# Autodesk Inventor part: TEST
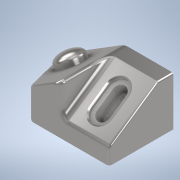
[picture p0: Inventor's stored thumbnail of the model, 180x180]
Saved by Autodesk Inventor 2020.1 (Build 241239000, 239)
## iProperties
Created: 2019-11
Part Number: TEST
Material: Stainless Steel, 440C
Document SubType Name: Modeling
Designer: Synergysoft Dell02
Density: 7.75 g/cm^3
Appearance: Semi-Polished
Author: Synergysoft Dell02
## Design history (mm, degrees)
sketch "Sketch1"
  geometry: L1 (0, 0)-(-62, 0); L2 (-62, 0)-(-62, -50); L3 (-62, -50)-(18, -50); L4 (18, -50)-(18, -38); L5 (18, -38)-(0, 0)
  constraints: 10 end point, 3 perpendicular, 1 horizontal
  dimensions: "d0" = 62 distance of L1.start L1.end; "d1" = 50 distance of L1.end L2.end; "d2" = 80 distance of L2.end L3.end; "d3" = 12 distance of L3.end L4.end
extrude "Extrusion1" new body sketch "Sketch1" distance "d4" = 38; taper "d5" = 0 deg
workplane "Work Plane3"
workplane "Work Plane4"
workaxis "Work Axis1"
feature "Sculpt1"
  workplane "Work Plane6"
workplane "Work Plane7"
  workaxis "Work Axis4"
sketch "Sketch4"
  geometry: L1 (-50, 0)-(-50, 49.396) reference; L2 (-50, 49.396)-(-38, 49.396) reference; L3 (-38, 49.396)-(0, 28.226) reference; L4 (0, 28.226)-(0, 0) reference; L5 (0, 0)-(-38, 0) reference; L6 (-38, 0)-(-50, 0) reference; L7 (-50, 0)-(-50, 49.396) reference; L8 (0, 28.226)-(0, 0) reference; L9 (0, 0)-(-38, 0) reference; L10 (-38, 0)-(-50, 0) reference; L11 (-50, 49.396)-(-38, 49.396) reference; L12 (-38, 49.396)-(0, 28.226) reference; 1 further point
extrude "Extrusion4" cut sketch "Sketch4" extent not by distance; stored distance "d16" = 14.696; taper "d17" = 0 deg
sketch "Sketch5"
  geometry: L1 (19, 30.522)-(19, 15.522); L2 (14, 30.522)-(14, 15.522); L3 (24, 15.522)-(24, 30.522); L4 (38, 46.043)-(0, 46.043) reference; L5 (38, 0)-(38, 46.043) reference; L6 (11, 30.522)-(11, 15.522); L7 (27, 15.522)-(27, 30.522); A1 r 5 centre (19, 30.522) between (24, 30.522) and (14, 30.522); A2 r 5 centre (19, 15.522) between (14, 15.522) and (24, 15.522); A3 r 8 centre (19, 15.522) between (11, 15.522) and (27, 15.522); A4 r 8 centre (19, 30.522) between (27, 30.522) and (11, 30.522); 4 further points
  constraints: 12 end point, 8 point on circle, 4 centre point, 4 tangent, 3 midpoint, 2 parallel, 1 horizontal alignment, 1 vertical, 1 vertical alignment, 3 other
  dimensions: "d23" = 15 distance of L1.start L1.end; "d24" = 5 radius of A1; "d25" = 3 radial gap between concentric circles of A1 A4
extrude "Extrusion5" cut sketch "Sketch5" distance "d26" = 10; taper "d27" = 0 deg
extrude "Extrusion6" cut sketch "Sketch5" distance "d28" = 3; taper "d29" = 0 deg
fillet "Fillet1" dims "d18" = 5
fillet "Fillet2" dims "d19" = 5
fillet "Fillet3" dims "d20" = 10
fillet "Fillet4" dims "d21" = 2
fillet "Fillet5" dims "d22" = 2
chamfer "Chamfer1" distance "d30" = 1; stored, may be unused: second distance "d31" = 2, angle "d32" = 45 deg
sketch "Sketch6"
  geometry: A1 r 5 centre (19, 30.522) between (24, 30.522) and (14, 30.522) reference; A2 r 5 centre (19, 15.522) between (14, 15.522) and (24, 15.522) reference; 3 further points
  constraints: 2 coincident
hole "Hole1" sketch "Sketch6" at (19, 30.522), (19, 15.522) diameter "d33" = 3; stored, may be unused: countersink angle "d37" = 90 deg, drill point angle "d39" = 118 deg; dims "d34" = 6, "d35" = 5, "d36" = 2, "d38" = 8
sketch "Sketch7"
  geometry: L1 (-48.282, 50)-(-2.845, 50) reference; L2 (-49.983, 50)-(-49.983, 39.124) reference; C1 r 10 at (-24.983, 30); 1 further point
  constraints: 1 centre point
  dimensions: "d40" = 20 diameter of C1; "d41" = 20 distance from line of C1.centre L1; "d42" = 25 distance from line of C1.centre L2
extrude "Extrusion7" join sketch "Sketch7" distance "d43" = 3; taper "d44" = 0 deg
workplane "Work Plane8"
sketch "Sketch8"
  geometry: C1 r 10 at (0, 0) reference; 1 further point
loft "Loft1" sketch "Sketch8" dims "d46" = 10, "d47" = 90 deg, "d48" = 10, "d49" = 90 deg
  node "Edges1"
workplane "Work Plane1"
sketch "Sketch2"
  geometry: L1 (0, 12)-(38, 38); L2 (38, 38)-(0, 38) reference; L3 (38, 38)-(38, 45.681); L4 (38, 45.681)-(-14.226, 45.681); L5 (-14.226, 45.681)-(-14.226, 12); L6 (-14.226, 12)-(0, 12); L7 (50, 0)-(50, 38) reference; 1 further point
  constraints: 10 end point, 3 perpendicular, 1 point on line, 1 vertical
  dimensions: "d7" = 12 distance of point (0, 0) L1.start; "d8" = 12 distance from line of L7 L1.end
extrude "Extrusion2" cut sketch "Sketch2" extent not by distance; stored distance "d9" = 38; taper "d10" = 0 deg
workpoint "Work Point1"
workplane "Work Plane2"
sketch "Sketch3"
  geometry: L1 (0, 0)-(11.837, 64.745) reference; L2 (44.944, 0)-(0, 0) reference; 1 further point; 1 other entity
  constraints: 1 other
extrude "Extrusion3" cut sketch "Sketch3" extent not by distance; stored distance "d11" = 39.85; taper "d12" = 0 deg
body "Solid1"
workplane "Work Plane5"
workaxis "Work Axis2"
workaxis "Work Axis3"
node "Projected Loop1"
node "Project Cut Edges1"
node "Project Cut Edges2"
node "Project Cut Edges3"
other parameters: "d6" = -38, "d13" = -38, "d14" = -12, "d15" = -12, "d45" = 5
